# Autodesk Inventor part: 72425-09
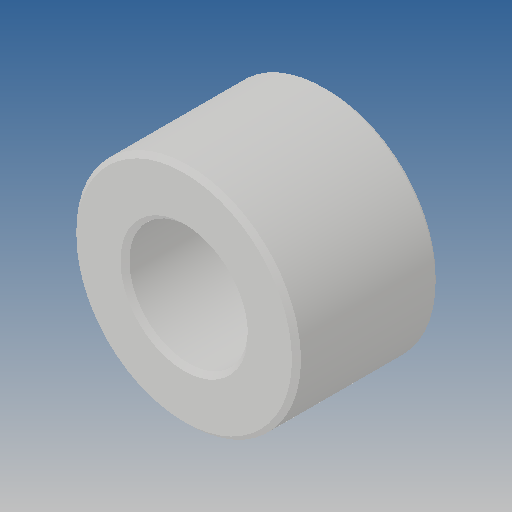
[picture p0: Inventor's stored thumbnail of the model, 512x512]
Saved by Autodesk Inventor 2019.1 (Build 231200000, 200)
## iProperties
Created: 2012-10
Part Number: 72425-09
Material: Ogólny
Document SubType Name: Modeling
Designer: CADENGINEERING4
Density: 1 g/cm^3
Appearance: Domyślna
Author: CADENGINEERING4
Revision Number: ÈÎºÎ
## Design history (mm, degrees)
feature "ÊäÈë1"
node "Bryła1"
